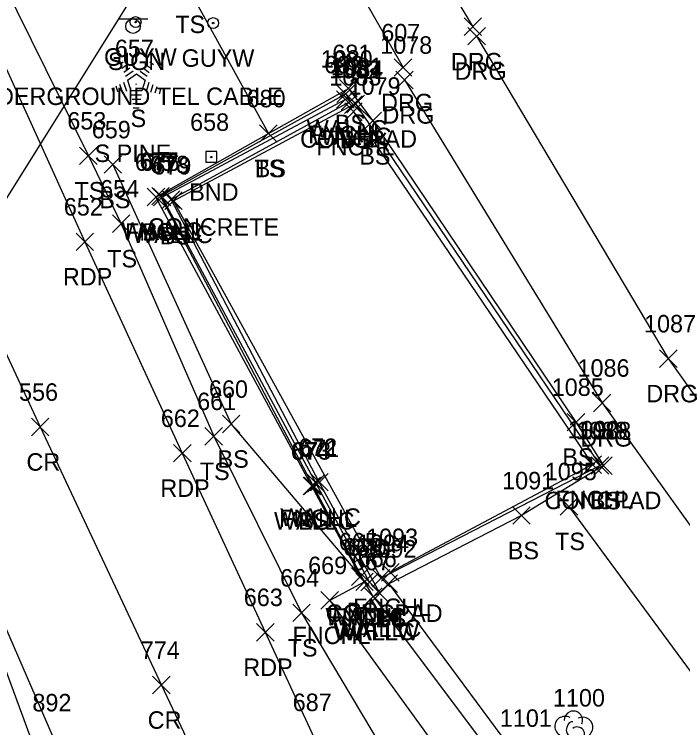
# Model space of a CAD drawing. Extents: x 1647133 to 1649138, y 411736 to 414924.
# Drawn here: x 1648612.6 to 1648689, y 412193.6 to 412275.3 of the extents above; entities that cross this region are included whole.
import ezdxf

# ---------------------------------------------------------------- set-up
doc = ezdxf.new("R2010")
doc.units = 0
for name, color, linetype in [('DCP', 7, 'Continuous'), ('L_A', 7, 'Continuous'), ('L_C', 7, 'Continuous'), ('L_I', 7, 'Continuous'), ('L_TIC', 7, 'Continuous'), ('LELB', 7, 'Continuous'), ('Level 18', 7, 'Continuous'), ('LFNC', 7, 'Continuous'), ('LS', 7, 'Continuous'), ('LTC', 7, 'Continuous'), ('LTD', 7, 'Continuous'), ('LW', 7, 'Continuous'), ('M_A', 7, 'Continuous'), ('M_C', 7, 'Continuous'), ('M_I', 7, 'Continuous'), ('P_A', 7, 'Continuous'), ('P_I', 7, 'Continuous'), ('P_TIC', 7, 'Continuous'), ('PET', 7, 'Continuous'), ('PRC', 7, 'Continuous'), ('R_A', 7, 'Continuous'), ('R_I', 7, 'Continuous'), ('R_TIC', 7, 'Continuous'), ('RDG', 7, 'Continuous'), ('S_A', 7, 'Continuous'), ('S_C', 7, 'Continuous'), ('SSGN', 7, 'Continuous'), ('U_A', 7, 'Continuous'), ('UPGW', 7, 'Continuous')]:
    doc.layers.add(name, color=color, linetype=linetype)

msp = doc.modelspace()

# ---------------------------------------------------------------- linework, layer by layer
at = {"layer": 'DCP'}
for points in [[(1648599.372, 412234.61), (1648633.995, 412290.01)], [(1648599.469, 412233.061), (1648621.957, 412171.977)]]:
    msp.add_lwpolyline(points, dxfattribs=at)
at = {"layer": 'L_TIC'}
for points in [[(1648649.774, 412265.813), (1648651.774, 412267.813)], [(1648651.774, 412265.813), (1648649.774, 412267.813)], [(1648649.465, 412265.184), (1648651.465, 412267.184)], [(1648651.465, 412265.184), (1648649.465, 412267.184)], [(1648649.422, 412264.539), (1648651.422, 412266.539)], [(1648651.422, 412264.539), (1648649.422, 412266.539)], [(1648649.965, 412264.319), (1648651.965, 412266.319)], [(1648651.965, 412264.319), (1648649.965, 412266.319)], [(1648649.965, 412264.319), (1648651.965, 412266.319)], [(1648651.965, 412264.319), (1648649.965, 412266.319)], [(1648650.347, 412263.957), (1648652.347, 412265.957)], [(1648652.347, 412263.957), (1648650.347, 412265.957)], [(1648650.606, 412264.028), (1648652.606, 412266.028)], [(1648652.606, 412264.028), (1648650.606, 412266.028)], [(1648650.364, 412263.142), (1648652.364, 412265.142)], [(1648652.364, 412263.142), (1648650.364, 412265.142)], [(1648652.575, 412262.089), (1648654.575, 412264.089)], [(1648654.575, 412262.089), (1648652.575, 412264.089)], [(1648640.62, 412260.648), (1648642.62, 412262.648)], [(1648642.62, 412260.648), (1648640.62, 412262.648)], [(1648640.62, 412260.648), (1648642.62, 412262.648)], [(1648642.62, 412260.648), (1648640.62, 412262.648)], [(1648620.029, 412258.099), (1648622.029, 412260.099)], [(1648622.029, 412258.099), (1648620.029, 412260.099)], [(1648622.835, 412257.098), (1648624.835, 412259.098)], [(1648624.835, 412257.098), (1648622.835, 412259.098)], [(1648627.763, 412253.382), (1648629.763, 412255.382)], [(1648629.763, 412253.382), (1648627.763, 412255.382)], [(1648628.287, 412253.477), (1648630.287, 412255.477)], [(1648630.287, 412253.477), (1648628.287, 412255.477)], [(1648628.47, 412253.37), (1648630.47, 412255.37)], [(1648630.47, 412253.37), (1648628.47, 412255.37)], [(1648629.499, 412253.102), (1648631.499, 412255.102)], [(1648631.499, 412253.102), (1648629.499, 412255.102)], [(1648629.761, 412252.957), (1648631.761, 412254.957)], [(1648631.761, 412252.957), (1648629.761, 412254.957)], [(1648623.781, 412250.326), (1648625.781, 412252.326)], [(1648625.781, 412250.326), (1648623.781, 412252.326)], [(1648636.368, 412227.397), (1648638.368, 412229.397)], [(1648638.368, 412227.397), (1648636.368, 412229.397)], [(1648675.806, 412227.616), (1648677.806, 412229.616)], [(1648677.806, 412227.616), (1648675.806, 412229.616)], [(1648634.367, 412225.993), (1648636.367, 412227.993)], [(1648636.367, 412225.993), (1648634.367, 412227.993)], [(1648677.711, 412222.756), (1648679.711, 412224.756)], [(1648679.711, 412222.756), (1648677.711, 412224.756)], [(1648678.562, 412222.654), (1648680.562, 412224.654)], [(1648680.562, 412222.654), (1648678.562, 412224.654)], [(1648678.956, 412222.635), (1648680.956, 412224.635)], [(1648680.956, 412222.635), (1648678.956, 412224.635)], [(1648645.596, 412220.306), (1648647.596, 412222.306)], [(1648647.596, 412220.306), (1648645.596, 412222.306)], [(1648645.733, 412220.325), (1648647.733, 412222.325)], [(1648647.733, 412220.325), (1648645.733, 412222.325)], [(1648646.095, 412220.609), (1648648.095, 412222.609)], [(1648648.095, 412220.609), (1648646.095, 412222.609)], [(1648646.445, 412220.745), (1648648.445, 412222.745)], [(1648648.445, 412220.745), (1648646.445, 412222.745)], [(1648675.009, 412217.968), (1648677.009, 412219.968)], [(1648677.009, 412217.968), (1648675.009, 412219.968)], [(1648669.57, 412216.924), (1648671.57, 412218.924)], [(1648671.57, 412216.924), (1648669.57, 412218.924)], [(1648654.569, 412210.431), (1648656.569, 412212.431)], [(1648656.569, 412210.431), (1648654.569, 412212.431)], [(1648651.141, 412209.937), (1648653.141, 412211.937)], [(1648653.141, 412209.937), (1648651.141, 412211.937)], [(1648653.531, 412209.754), (1648655.531, 412211.754)], [(1648655.531, 412209.754), (1648653.531, 412211.754)], [(1648651.618, 412209.345), (1648653.618, 412211.345)], [(1648653.618, 412209.345), (1648651.618, 412211.345)], [(1648651.618, 412209.345), (1648653.618, 412211.345)], [(1648653.618, 412209.345), (1648651.618, 412211.345)], [(1648652.186, 412209.303), (1648654.186, 412211.303)], [(1648654.186, 412209.303), (1648652.186, 412211.303)], [(1648654.389, 412209.124), (1648656.389, 412211.124)], [(1648656.389, 412209.124), (1648654.389, 412211.124)], [(1648653.363, 412208.029), (1648655.363, 412210.029)], [(1648655.363, 412208.029), (1648653.363, 412210.029)], [(1648653.363, 412208.029), (1648655.363, 412210.029)], [(1648655.363, 412208.029), (1648653.363, 412210.029)], [(1648647.634, 412207.217), (1648649.634, 412209.217)], [(1648649.634, 412207.217), (1648647.634, 412209.217)], [(1648652.627, 412207.663), (1648654.627, 412209.663)], [(1648654.627, 412207.663), (1648652.627, 412209.663)], [(1648652.627, 412207.663), (1648654.627, 412209.663)], [(1648654.627, 412207.663), (1648652.627, 412209.663)], [(1648644.42, 412205.793), (1648646.42, 412207.793)], [(1648646.42, 412205.793), (1648644.42, 412207.793)]]:
    msp.add_lwpolyline(points, dxfattribs=at)
at = {"layer": 'LELB'}
for points in [[(1648569.547, 412372.007), (1648582.324, 412342.107), (1648598.266, 412308.648), (1648609.531, 412282.347), (1648621.029, 412259.099), (1648624.781, 412251.326), (1648635.367, 412226.993), (1648645.42, 412206.793), (1648666.114, 412172.04)], [(1648587.046, 412344.259), (1648604.421, 412312.299), (1648614.561, 412284.925), (1648632.566, 412278.144), (1648641.62, 412261.648)], [(1648623.835, 412258.098), (1648637.368, 412228.397), (1648652.141, 412210.937), (1648646.596, 412221.306), (1648628.763, 412254.382), (1648641.62, 412261.648), (1648650.774, 412266.813), (1648653.575, 412263.089), (1648676.806, 412228.616), (1648679.956, 412223.635), (1648670.57, 412217.924), (1648655.389, 412210.124), (1648669.737, 412190.746), (1648683.773, 412170.473), (1648710.631, 412136.174)], [(1648630.761, 412253.957), (1648651.347, 412264.957)], [(1648676.009, 412218.968), (1648692.131, 412197.077), (1648701.168, 412183.34)]]:
    msp.add_lwpolyline(points, dxfattribs=at)
at = {"layer": 'Level 18'}
for p, q in [((1648635.727, 412259.609), (1648634.477, 412259.609)), ((1648634.477, 412259.609), (1648634.477, 412258.359)), ((1648635.727, 412259.609), (1648634.477, 412259.609)), ((1648634.477, 412259.609), (1648634.477, 412258.359)), ((1648635.727, 412258.359), (1648635.727, 412259.609)), ((1648635.727, 412258.359), (1648635.727, 412259.609)), ((1648634.477, 412258.359), (1648635.727, 412258.359)), ((1648634.477, 412258.359), (1648635.727, 412258.359))]:
    msp.add_line(p, q, dxfattribs=at)
msp.add_circle((1648635.078, 412258.947), 0.0833, dxfattribs=at)
at = {"layer": 'LFNC'}
for points in [[(1648653.186, 412210.303), (1648647.095, 412221.609), (1648629.47, 412254.37), (1648650.422, 412265.539)], [(1648651.364, 412264.142), (1648678.711, 412223.756), (1648655.569, 412211.431)], [(1648652.618, 412210.345), (1648648.634, 412208.217), (1648679.397, 412165.798), (1648683.471, 412168.596)]]:
    msp.add_lwpolyline(points, dxfattribs=at)
at = {"layer": 'LS'}
for points in [[(1648651.606, 412265.028), (1648679.562, 412223.654), (1648654.531, 412210.754)], [(1648654.531, 412210.754), (1648630.761, 412253.957)]]:
    msp.add_lwpolyline(points, dxfattribs=at)
at = {"layer": 'LTC'}
for p, q in [((1648624.665, 412269.594), (1648625.019, 412269.852)), ((1648624.874, 412269.129), (1648625.404, 412269.513)), ((1648627.692, 412269.486), (1648628.242, 412269.087)), ((1648628.063, 412269.835), (1648628.482, 412269.53)), ((1648625.084, 412268.663), (1648625.788, 412269.174)), ((1648625.294, 412268.197), (1648626.172, 412268.835)), ((1648626.95, 412268.79), (1648627.759, 412268.201)), ((1648627.321, 412269.138), (1648628, 412268.644)), ((1648625.518, 412267.742), (1648626.53, 412268.477)), ((1648625.518, 412267.742), (1648625.905, 412266.549)), ((1648626.53, 412268.477), (1648627.527, 412267.752)), ((1648627.527, 412267.752), (1648627.136, 412266.549)), ((1648624.153, 412267.09), (1648624.364, 412266.439)), ((1648624.608, 412267.307), (1648624.879, 412266.471)), ((1648625.064, 412267.523), (1648625.394, 412266.504)), ((1648627.964, 412267.481), (1648627.627, 412266.441)), ((1648628.409, 412267.231), (1648628.122, 412266.346)), ((1648628.854, 412266.981), (1648628.617, 412266.251)), ((1648623.697, 412266.874), (1648623.849, 412266.406)), ((1648627.136, 412266.549), (1648625.905, 412266.549)), ((1648629.298, 412266.73), (1648629.111, 412266.156)), ((1648627.097, 412266.049), (1648625.953, 412266.049)), ((1648627.014, 412265.549), (1648626.025, 412265.549)), ((1648626.93, 412265.049), (1648626.098, 412265.049)), ((1648626.846, 412264.549), (1648626.171, 412264.549))]:
    msp.add_line(p, q, dxfattribs=at)
at = {"layer": 'LTD'}
msp.add_arc((1648676.511, 412194.504), 1.047, 335.52715, 180.95627, dxfattribs=at)
for centre, major_axis, ratio, start_param, end_param in [((1648675.672, 412193.737), (1.21, -0.512), 0.895232, 1.570796, 4.712389), ((1648676.255, 412193.529), (-0.208, -0.792), 0.645439, 3.141593, 6.283185), ((1648677.505, 412193.654), (-1.141, -0.483), 0.949671, 1.570796, 4.712389), ((1648676.964, 412192.904), (-0.5, 0.667), 0.989748, 3.141593, 6.283185)]:
    msp.add_ellipse(centre, major_axis=major_axis, ratio=ratio, start_param=start_param, end_param=end_param, dxfattribs=at)
at = {"layer": 'LW'}
for points in [[(1648654.363, 412209.029), (1648653.627, 412208.663), (1648652.618, 412210.345), (1648646.733, 412221.325), (1648629.287, 412254.477), (1648650.465, 412266.184), (1648650.965, 412265.319)], [(1648654.363, 412209.029), (1648647.445, 412221.745), (1648630.499, 412254.102), (1648650.965, 412265.319)], [(1648653.627, 412208.663), (1648682.946, 412169.571)]]:
    msp.add_lwpolyline(points, dxfattribs=at)
at = {"layer": 'P_TIC'}
for points in [[(1648619.629, 412248.259), (1648621.629, 412250.259)], [(1648621.629, 412248.259), (1648619.629, 412250.259)], [(1648614.514, 412227.06), (1648616.514, 412229.06)], [(1648616.514, 412227.06), (1648614.514, 412229.06)], [(1648630.777, 412224.06), (1648632.777, 412226.06)], [(1648632.777, 412224.06), (1648630.777, 412226.06)], [(1648640.267, 412203.566), (1648642.267, 412205.566)], [(1648642.267, 412203.566), (1648640.267, 412205.566)], [(1648628.383, 412197.525), (1648630.383, 412199.525)], [(1648630.383, 412197.525), (1648628.383, 412199.525)]]:
    msp.add_lwpolyline(points, dxfattribs=at)
at = {"layer": 'PET'}
for points in [[(1648536.119, 412432.998), (1648543.399, 412417.954), (1648546.486, 412415.003), (1648562.248, 412380.849), (1648562.337, 412375.739), (1648565.289, 412369.171), (1648579.297, 412340.19), (1648594.414, 412306.778), (1648606.351, 412280.635), (1648620.629, 412249.259), (1648631.777, 412225.06), (1648641.267, 412204.566), (1648646.814, 412192.55), (1648664.816, 412155.812), (1648677.431, 412126.914), (1648681.854, 412118.139), (1648693.972, 412097.362), (1648709.507, 412075.411), (1648723.887, 412057.125), (1648746.982, 412031.15), (1648768.696, 412011.078), (1648794.521, 411987.621), (1648826.406, 411959.789)], [(1648512.544, 412422.792), (1648530.09, 412384.206), (1648549.578, 412341.858), (1648567.717, 412302.186), (1648584.888, 412264.911), (1648603.961, 412222.556), (1648616.989, 412192.513), (1648626.592, 412174.015), (1648634.702, 412156.346), (1648647.722, 412129.202), (1648659.195, 412106.441), (1648667.013, 412092.615), (1648674.657, 412079.411), (1648685.658, 412062.516), (1648700.073, 412044.859), (1648717.467, 412025.769), (1648741.246, 412001.123), (1648755.318, 411988.116), (1648772.85, 411971.957)]]:
    msp.add_lwpolyline(points, dxfattribs=at)
at = {"layer": 'PRC'}
msp.add_lwpolyline([(1648523.855, 412428.164), (1648541.762, 412388.819), (1648560.786, 412347.218), (1648578.952, 412307.656), (1648596.522, 412268.849), (1648615.514, 412228.06), (1648629.383, 412198.525), (1648645.407, 412164.541), (1648659.578, 412134.14), (1648672.041, 412110.748), (1648683.898, 412091.11), (1648700.383, 412068.335), (1648715.839, 412049.98), (1648739.601, 412024.905), (1648761.868, 412004.355), (1648787.636, 411981.064), (1648820.993, 411950.624), (1648837.381, 411936.249), (1648865.129, 411910.894), (1648893.845, 411885.618), (1648930.35, 411852.903), (1648951.421, 411834.103), (1648988.1, 411800.425), (1649025.041, 411766.663)], dxfattribs=at)
at = {"layer": 'R_TIC'}
for points in [[(1648664.014, 412272.87), (1648666.014, 412274.87)], [(1648666.014, 412272.87), (1648664.014, 412274.87)], [(1648664.441, 412271.797), (1648666.441, 412273.797)], [(1648666.441, 412271.797), (1648664.441, 412273.797)], [(1648656.023, 412268.194), (1648658.023, 412270.194)], [(1648658.023, 412268.194), (1648656.023, 412270.194)], [(1648656.183, 412266.776), (1648658.183, 412268.776)], [(1648658.183, 412266.776), (1648656.183, 412268.776)], [(1648686.368, 412234.883), (1648688.368, 412236.883)], [(1648688.368, 412234.883), (1648686.368, 412236.883)], [(1648678.811, 412229.814), (1648680.811, 412231.814)], [(1648680.811, 412229.814), (1648678.811, 412231.814)]]:
    msp.add_lwpolyline(points, dxfattribs=at)
at = {"layer": 'RDG'}
for points in [[(1648536.119, 412432.998), (1648547.131, 412425.133), (1648565.195, 412415.408), (1648582.412, 412411.665), (1648597.829, 412393.338), (1648613.482, 412368.054), (1648631.942, 412343.809), (1648651.807, 412314.197), (1648648.533, 412301.447), (1648665.014, 412273.87)], [(1648565.289, 412369.171), (1648569.547, 412372.007), (1648573.916, 412378.2), (1648579.707, 412376.638), (1648596.712, 412356.354), (1648610.62, 412329.914), (1648623.298, 412310.38), (1648639.159, 412296.808), (1648644.936, 412290.352), (1648657.023, 412269.194)], [(1648665.441, 412272.797), (1648687.368, 412235.883), (1648707.36, 412207.822), (1648732.67, 412172.62), (1648752.06, 412147.321), (1648777.802, 412111.4), (1648801.739, 412083.078)], [(1648657.183, 412267.776), (1648679.811, 412230.814), (1648700.282, 412202.253), (1648725.639, 412167.846), (1648744.327, 412141.94), (1648771.48, 412106.331), (1648789.563, 412079.997), (1648790.942, 412077.169)]]:
    msp.add_lwpolyline(points, dxfattribs=at)
at = {"layer": 'SSGN'}
for p, q in [((1648624.489, 412274.765), (1648627.823, 412274.765)), ((1648626.136, 412273.932), (1648626.136, 412273.932))]:
    msp.add_line(p, q, dxfattribs=at)
msp.add_circle((1648626.136, 412273.932), 0.833, dxfattribs=at)
at = {"layer": 'UPGW'}
for centre, radius in [((1648626.425, 412274.403), 0.625), ((1648626.425, 412274.403), 0.0833), ((1648635.304, 412274.286), 0.625), ((1648635.304, 412274.286), 0.0833)]:
    msp.add_circle(centre, radius, dxfattribs=at)

# ---------------------------------------------------------------- texts
at = {"layer": 'L_A'}
for s, p in [('TS', (1648630.975, 412273.144)), ('S', (1648625.856, 412262.386)), ('BS', (1648649.215, 412261.813)), ('WALLC', (1648646, 412261.184)), ('CONCPAD', (1648645.251, 412260.028)), ('FNCHL', (1648646.17, 412260.539)), ('WALLC', (1648646.501, 412260.319)), ('WALLC', (1648646.501, 412260.319)), ('BS', (1648649.788, 412259.957)), ('FNCHL', (1648647.112, 412259.142)), ('BS', (1648652.016, 412258.089)), ('TS', (1648640.03, 412256.648)), ('BS', (1648640.061, 412256.648)), ('TS', (1648619.438, 412254.099)), ('BS', (1648622.276, 412253.098)), ('WALLC', (1648624.822, 412249.477)), ('BS', (1648627.204, 412249.382)), ('FNCHL', (1648625.218, 412249.37)), ('WALLC', (1648626.034, 412249.102)), ('BS', (1648629.202, 412248.957)), ('TS', (1648623.19, 412246.326)), ('BS', (1648635.809, 412223.397)), ('BS', (1648675.247, 412223.616)), ('TS', (1648633.777, 412221.993)), ('CONCPAD', (1648673.208, 412218.654)), ('FNCHL', (1648674.46, 412218.756)), ('BS', (1648678.397, 412218.635)), ('WALLC', (1648642.981, 412216.745)), ('WALLC', (1648642.268, 412216.325)), ('FNCHL', (1648642.843, 412216.609)), ('BS', (1648645.037, 412216.306)), ('TS', (1648674.418, 412213.968)), ('BS', (1648669.011, 412212.924)), ('FNCHL', (1648651.317, 412206.431)), ('WALLC', (1648648.153, 412205.345)), ('CONCPAD', (1648648.177, 412205.754)), ('FNCHL', (1648648.366, 412205.345)), ('FNCHL', (1648648.934, 412205.303)), ('BS', (1648650.581, 412205.937)), ('BS', (1648653.83, 412205.124)), ('WALLC', (1648649.162, 412203.663)), ('WALLC', (1648649.898, 412204.029)), ('WALLC', (1648649.898, 412204.029)), ('FNCHL', (1648644.382, 412203.217)), ('WALLW', (1648649.044, 412203.663)), ('TS', (1648643.829, 412201.793))]:
    msp.add_text(s, height=2, dxfattribs=at).set_placement(p)
at = {"layer": 'L_C'}
msp.add_text('S PINE', height=2, dxfattribs=at).set_placement((1648621.745, 412258.386))
at = {"layer": 'L_I'}
for s, p in [('657', (1648624.06, 412270.386)), ('681', (1648648.931, 412269.813)), ('1080', (1648647.607, 412269.184)), ('682', (1648648.013, 412268.539)), ('1081', (1648648.76, 412268.319)), ('1081', (1648648.76, 412268.319)), ('1082', (1648648.576, 412267.957)), ('1084', (1648648.834, 412268.028)), ('1083', (1648648.592, 412267.142)), ('1079', (1648650.795, 412266.089)), ('680', (1648639.124, 412264.648)), ('680', (1648639.124, 412264.648)), ('653', (1648618.619, 412262.099)), ('659', (1648621.418, 412261.098)), ('675', (1648626.353, 412257.382)), ('677', (1648626.878, 412257.477)), ('676', (1648627.005, 412257.37)), ('678', (1648628.089, 412257.102)), ('679', (1648628.344, 412256.957)), ('654', (1648622.371, 412254.326)), ('1085', (1648674.034, 412231.616)), ('660', (1648634.824, 412231.397)), ('661', (1648633.477, 412229.993)), ('1090', (1648675.853, 412226.756)), ('1089', (1648676.782, 412226.654)), ('1088', (1648677.185, 412226.635)), ('674', (1648644.187, 412224.306)), ('673', (1648644.324, 412224.325)), ('672', (1648645.036, 412224.745)), ('671', (1648645.252, 412224.609)), ('1095', (1648673.237, 412221.968)), ('1091', (1648668.365, 412220.924)), ('1093', (1648652.797, 412214.431)), ('665', (1648649.684, 412213.937)), ('1094', (1648651.759, 412213.754)), ('668', (1648650.161, 412213.345)), ('668', (1648650.161, 412213.345)), ('670', (1648650.69, 412213.303)), ('1092', (1648652.617, 412213.124)), ('666', (1648651.851, 412212.029)), ('666', (1648651.851, 412212.029)), ('669', (1648646.169, 412211.217)), ('667', (1648651.17, 412211.663)), ('667', (1648651.17, 412211.663)), ('664', (1648642.963, 412209.793)), ('1100', (1648674.172, 412196.07)), ('1101', (1648668.1, 412193.746))]:
    msp.add_text(s, height=2, dxfattribs=at).set_placement(p)
at = {"layer": 'LTC'}
msp.add_text('.', height=1.037, rotation=270, dxfattribs=at).set_placement((1648626.412, 412267.49))
at = {"layer": 'M_A'}
msp.add_text('BND', height=2, dxfattribs=at).set_placement((1648632.565, 412253.952))
at = {"layer": 'M_C'}
msp.add_text('CONCRETE', height=2, dxfattribs=at).set_placement((1648627.832, 412249.952))
at = {"layer": 'M_I'}
msp.add_text('658', height=2, dxfattribs=at).set_placement((1648632.667, 412261.952))
at = {"layer": 'P_A'}
for s, p in [('RDP', (1648618.117, 412244.259)), ('CR', (1648613.947, 412223.06)), ('RDP', (1648629.265, 412220.06)), ('RDP', (1648638.755, 412199.566)), ('CR', (1648627.816, 412193.525))]:
    msp.add_text(s, height=2, dxfattribs=at).set_placement(p)
at = {"layer": 'P_I'}
for s, p in [('652', (1648618.22, 412252.259)), ('556', (1648613.097, 412231.06)), ('662', (1648629.32, 412228.06)), ('663', (1648638.811, 412207.566)), ('774', (1648627.02, 412201.525)), ('892', (1648614.626, 412195.513)), ('892', (1648614.626, 412195.513)), ('687', (1648644.404, 412195.55)), ('687', (1648644.404, 412195.55))]:
    msp.add_text(s, height=2, dxfattribs=at).set_placement(p)
at = {"layer": 'R_A'}
for p in [(1648662.502, 412268.87), (1648662.93, 412267.797), (1648654.511, 412264.194), (1648654.671, 412262.776), (1648684.856, 412230.883), (1648677.299, 412225.814)]:
    msp.add_text('DRG', height=2, dxfattribs=at).set_placement(p)
at = {"layer": 'R_I'}
for s, p in [('607', (1648654.535, 412272.194)), ('1078', (1648654.411, 412270.776)), ('1087', (1648684.596, 412238.883)), ('1086', (1648676.984, 412233.814))]:
    msp.add_text(s, height=2, dxfattribs=at).set_placement(p)
at = {"layer": 'S_A'}
msp.add_text('SIGN', height=2, dxfattribs=at).set_placement((1648623.274, 412268.912))
at = {"layer": 'S_C'}
msp.add_text('UNDERGROUND TEL CABLE', height=2, dxfattribs=at).set_placement((1648606.715, 412264.912))
at = {"layer": 'U_A'}
for p in [(1648622.819, 412269.403), (1648631.698, 412269.286)]:
    msp.add_text('GUYW', height=2, dxfattribs=at).set_placement(p)

doc.saveas('drawing.dxf')
